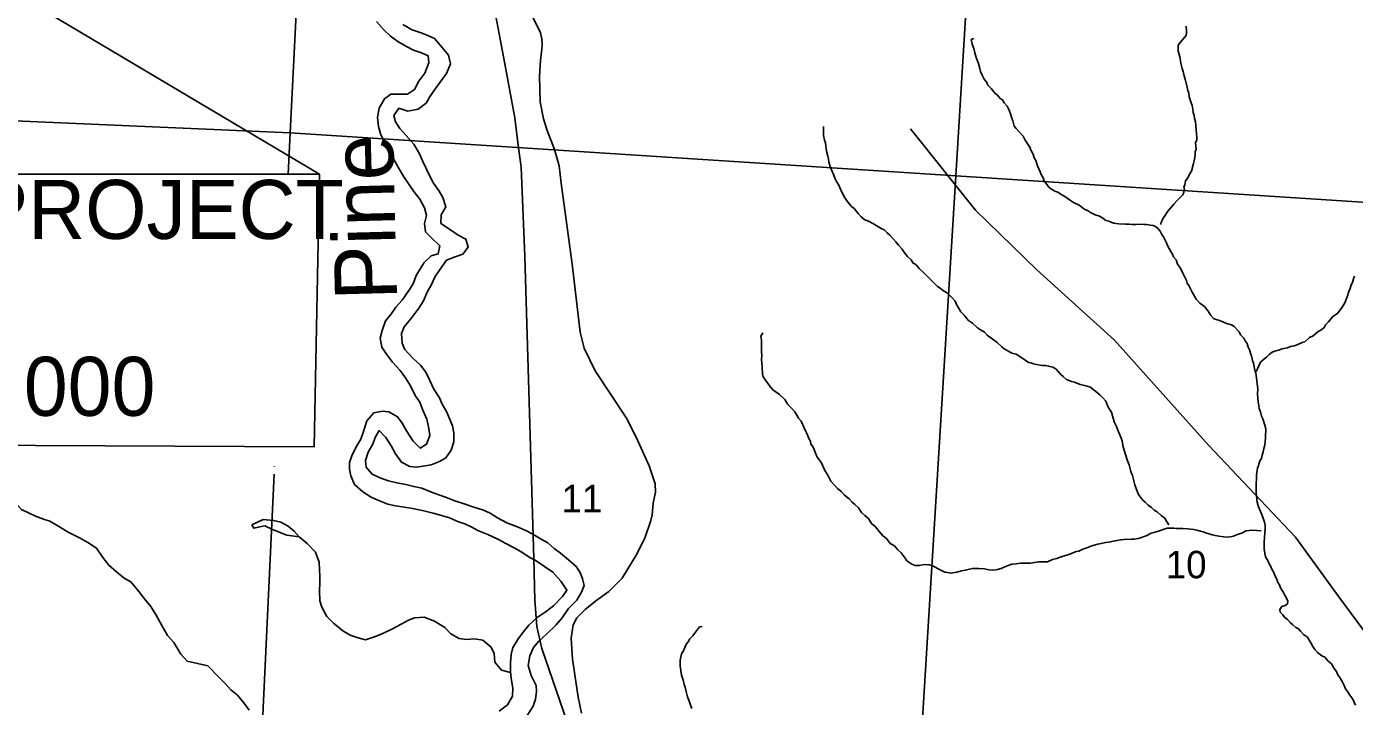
# Model space of a CAD drawing. Extents: x 0 to 82.7, y -0.2 to 22.
# Drawn here: x 3.348 to 5.374, y 17.584 to 18.621 of the extents above; entities that cross this region are included whole.
import ezdxf

# ---------------------------------------------------------------- set-up
doc = ezdxf.new("R2010")
doc.units = 0
for name, color, linetype in [('Default', 7, 'Continuous'), ('GM_X_Minor_Lake', 7, 'Continuous'), ('GM_X_Minor_River', 7, 'Continuous'), ('GM_X_Minor_River_Text', 7, 'Continuous'), ('GM_X_Rail_Line', 7, 'Continuous'), ('GM_X_Section', 7, 'Continuous'), ('GM_X_Section_Text', 7, 'Continuous'), ('GM_X_State_Route', 7, 'Continuous'), ('GM_X_Township_Road', 7, 'Continuous'), ('SH_Data', 7, 'Continuous')]:
    doc.layers.add(name, color=color, linetype=linetype)

msp = doc.modelspace()

# ---------------------------------------------------------------- linework, layer by layer
at = {"layer": 'Default'}
msp.add_lwpolyline([(3.7948, 18.3961), (3.7869, 17.9798), (2.8306, 17.9843), (2.8367, 18.3961)], dxfattribs=at)
at = {"layer": 'GM_X_Minor_Lake'}
for points in [[(3.7639, 17.8425), (3.7564, 17.8511), (3.7473, 17.8591), (3.736, 17.8649), (3.7247, 17.8676), (3.7091, 17.8689), (3.6917, 17.861)], [(3.6917, 17.861), (3.695, 17.8557), (3.7015, 17.8571), (3.7117, 17.8594), (3.7234, 17.8536), (3.7453, 17.8451), (3.7639, 17.8425)]]:
    msp.add_lwpolyline(points, dxfattribs=at)
at = {"layer": 'GM_X_Minor_River'}
for points in [[(3.8822, 18.6291), (3.8936, 18.6158), (3.9035, 18.607), (3.9145, 18.5987), (3.9278, 18.591), (3.9385, 18.5853), (3.9506, 18.5811), (3.9609, 18.5766), (3.962, 18.5663), (3.9559, 18.5504), (3.9468, 18.5382), (3.9399, 18.5253), (3.9293, 18.5181), (3.9038, 18.5181), (3.8943, 18.5113), (3.886, 18.4968), (3.8837, 18.4824), (3.8848, 18.4687), (3.8886, 18.4561), (3.8958, 18.4428), (3.9038, 18.4272), (3.9106, 18.4147), (3.9171, 18.4033), (3.9235, 18.3923), (3.9322, 18.3793), (3.9391, 18.3698), (3.9482, 18.358), (3.955, 18.3447), (3.9581, 18.3329), (3.9554, 18.3208), (3.9565, 18.3082), (3.966, 18.2987), (3.9785, 18.2865), (3.9763, 18.2744), (3.9652, 18.2717), (3.9546, 18.2611), (3.9424, 18.2413), (3.9378, 18.2288), (3.9314, 18.2185), (3.9211, 18.2037), (3.9116, 18.1931), (3.904, 18.1821), (3.8956, 18.1722), (3.8907, 18.1574), (3.8876, 18.1456), (3.8903, 18.1323), (3.8971, 18.1216), (3.9062, 18.1091), (3.918, 18.0962), (3.9263, 18.0855), (3.9339, 18.0733), (3.9411, 18.0585), (3.948, 18.0479), (3.9529, 18.0361), (3.959, 18.0224), (3.9616, 18.0079), (3.9631, 17.9973), (3.9582, 17.984), (3.9487, 17.9779), (3.9381, 17.9886), (3.9278, 18.0045), (3.921, 18.0159), (3.9141, 18.0258), (3.9008, 18.0335), (3.8913, 18.0346), (3.8777, 18.0316), (3.867, 18.0194), (3.8624, 18.0031), (3.8579, 17.9917), (3.8506, 17.9788), (3.8442, 17.9662), (3.8407, 17.956), (3.8407, 17.9457), (3.8426, 17.9358), (3.8483, 17.9225), (3.8612, 17.9115), (3.8738, 17.9031), (3.884, 17.8985)], [(3.9653, 17.9523), (3.9779, 17.9576), (3.9878, 17.9629), (3.9958, 17.9747), (4, 17.9876), (4, 18.0013), (3.9981, 18.012), (3.9893, 18.0329), (3.9821, 18.045), (3.978, 18.0546), (3.9696, 18.0682), (3.9635, 18.0812), (3.9571, 18.0937), (3.9491, 18.1048), (3.9373, 18.1154), (3.9252, 18.1287), (3.9214, 18.1382), (3.9203, 18.1531), (3.9241, 18.1629), (3.9343, 18.1751), (3.9465, 18.1914), (3.9537, 18.2028), (3.9594, 18.2161), (3.9652, 18.2268), (3.9716, 18.2397), (3.9789, 18.2511), (3.9887, 18.2647), (4.0021, 18.2697), (4.0138, 18.2738), (4.0218, 18.2849), (4.0184, 18.297), (4.0066, 18.3031), (3.9949, 18.3111), (3.98, 18.321), (3.9808, 18.3339), (3.9877, 18.3465), (3.9831, 18.3605), (3.9778, 18.37), (3.9687, 18.3826), (3.9637, 18.3921), (3.9584, 18.4039), (3.9527, 18.4153), (3.947, 18.4282), (3.9387, 18.4419), (3.9273, 18.4552), (3.9178, 18.4659), (3.911, 18.4758), (3.9083, 18.4857), (3.9163, 18.4967), (3.9296, 18.4921), (3.9456, 18.4951), (3.9577, 18.5046), (3.9638, 18.5153), (3.9718, 18.527), (3.9889, 18.5498), (3.995, 18.5643), (3.9916, 18.5776), (3.9821, 18.5894), (3.9704, 18.6031), (3.9605, 18.608), (3.9502, 18.6118), (3.9365, 18.6164), (3.9221, 18.6248)], [(5.0777, 18.3194), (5.0793, 18.3235), (5.0813, 18.3277), (5.0847, 18.3326), (5.089, 18.3397), (5.0928, 18.3435), (5.0986, 18.3506), (5.1028, 18.3555), (5.112, 18.3645), (5.1136, 18.3687), (5.1144, 18.3725), (5.1137, 18.3763), (5.1149, 18.3801), (5.1161, 18.3857), (5.1195, 18.3903), (5.1219, 18.3952), (5.1254, 18.4008), (5.1285, 18.4122), (5.1293, 18.4163), (5.1306, 18.4247), (5.131, 18.4304), (5.1322, 18.4342), (5.1315, 18.4441), (5.1331, 18.4486), (5.1332, 18.4532), (5.1328, 18.4573), (5.1325, 18.4642), (5.1318, 18.4699), (5.1312, 18.476), (5.1297, 18.4817), (5.1294, 18.4855), (5.1279, 18.4901), (5.1272, 18.4954), (5.1261, 18.5011), (5.1247, 18.5049), (5.1225, 18.511), (5.1217, 18.5148), (5.121, 18.5198), (5.1196, 18.5236), (5.1181, 18.5312), (5.1159, 18.5389), (5.1141, 18.5461), (5.1123, 18.5526), (5.1112, 18.5572), (5.1101, 18.5617), (5.109, 18.5655), (5.1083, 18.5697), (5.1073, 18.5751), (5.1062, 18.5789), (5.1051, 18.5838), (5.1047, 18.5876), (5.1048, 18.593), (5.1083, 18.5975), (5.1137, 18.6035), (5.1171, 18.6076), (5.1175, 18.6118), (5.1176, 18.6156), (5.1173, 18.6221)], [(5.104, 18.259), (5.1018, 18.2655), (5.0977, 18.2701), (5.0962, 18.2739), (5.0936, 18.2781), (5.0914, 18.2827), (5.0888, 18.2873), (5.0873, 18.2915), (5.0851, 18.2953), (5.0825, 18.3003), (5.0798, 18.3041), (5.0776, 18.3091), (5.0743, 18.3129), (5.0705, 18.316), (5.0667, 18.3176), (5.0626, 18.3184), (5.0565, 18.3192), (5.0523, 18.3193), (5.0459, 18.3198), (5.0402, 18.3191), (5.0345, 18.3195), (5.0303, 18.3196), (5.0246, 18.3196), (5.0144, 18.3205), (5.0064, 18.3214), (4.9989, 18.3242), (4.9947, 18.3253), (4.9902, 18.3288), (4.9849, 18.3319), (4.9785, 18.3343), (4.9714, 18.3374), (4.9668, 18.3405), (4.9627, 18.3421), (4.9537, 18.349), (4.945, 18.353), (4.9405, 18.3561), (4.9307, 18.363), (4.9265, 18.365), (4.9213, 18.3685), (4.9167, 18.37), (4.9118, 18.3731), (4.9081, 18.3758), (4.9028, 18.3824), (4.9006, 18.3862), (4.8991, 18.3904), (4.8961, 18.3954), (4.8943, 18.3996), (4.8921, 18.4045), (4.8902, 18.4091), (4.8877, 18.4168), (4.8854, 18.421), (4.884, 18.4248), (4.8829, 18.4286), (4.8803, 18.4328), (4.8784, 18.4374), (4.8747, 18.4435), (4.8717, 18.4481), (4.8684, 18.4542), (4.862, 18.4615), (4.8579, 18.4658), (4.8549, 18.4696), (4.8538, 18.4734), (4.8527, 18.4776), (4.8509, 18.4818), (4.849, 18.4883), (4.8476, 18.4921), (4.8461, 18.4959), (4.8439, 18.5001), (4.8397, 18.5051), (4.8371, 18.5094), (4.8334, 18.5117), (4.8293, 18.5167), (4.8255, 18.5194), (4.8195, 18.5267), (4.8146, 18.5321), (4.8128, 18.5359), (4.8087, 18.5412), (4.8057, 18.5474), (4.8035, 18.5527), (4.8024, 18.5573), (4.8002, 18.5649), (4.7973, 18.5726), (4.7958, 18.5779), (4.7944, 18.5836), (4.7933, 18.5878), (4.7907, 18.5947), (4.7893, 18.6015), (4.7931, 18.6034)], [(4.6268, 18.3266), (4.6215, 18.3309), (4.6166, 18.3362), (4.6106, 18.3435), (4.6065, 18.347), (4.6028, 18.3509), (4.599, 18.3562), (4.596, 18.3608), (4.5934, 18.3654), (4.5897, 18.3734), (4.5875, 18.3795), (4.5838, 18.3849), (4.5816, 18.3891), (4.579, 18.3956), (4.5757, 18.4036), (4.5742, 18.4078), (4.572, 18.4143), (4.5717, 18.4196), (4.5706, 18.4235), (4.5688, 18.4292), (4.5677, 18.4345), (4.5674, 18.4395), (4.5667, 18.444), (4.5656, 18.4478), (4.5641, 18.4551), (4.5638, 18.46), (4.5639, 18.4688)], [(5.0907, 17.861), (5.0869, 17.8663), (5.0843, 17.8713), (5.0791, 17.8752), (5.0727, 17.8806), (5.0682, 17.8833), (5.0644, 17.8875), (5.0591, 17.891), (5.0546, 17.8956), (5.0505, 17.8991), (5.0442, 17.9072), (5.0412, 17.9148), (5.0386, 17.922), (5.0354, 17.9361), (5.0328, 17.9423), (5.0303, 17.9525), (5.0277, 17.9587), (5.0244, 17.9682), (5.0226, 17.9747), (5.0207, 17.9819), (5.0197, 17.9892), (5.0178, 17.9934), (5.016, 17.9983), (5.0138, 18.0029), (5.0108, 18.0109), (5.0075, 18.0182), (5.0031, 18.0327), (4.9983, 18.0403), (4.9946, 18.0495), (4.9901, 18.0545), (4.986, 18.0587), (4.9792, 18.0645), (4.9751, 18.0676), (4.9709, 18.0711), (4.9641, 18.0731), (4.96, 18.0743), (4.9554, 18.0751), (4.9467, 18.0786), (4.9422, 18.0798), (4.9346, 18.0826), (4.9298, 18.0868), (4.926, 18.0903), (4.9189, 18.0987), (4.9136, 18.1015), (4.9072, 18.1031), (4.9026, 18.1039), (4.8981, 18.1043), (4.8943, 18.1047), (4.889, 18.1056), (4.8841, 18.1064), (4.8803, 18.108), (4.8765, 18.1088), (4.8716, 18.1122), (4.8634, 18.1177), (4.8577, 18.1212), (4.8513, 18.1231), (4.8452, 18.1266), (4.8396, 18.1294), (4.8358, 18.1325), (4.8287, 18.139), (4.8212, 18.1448), (4.8137, 18.1506), (4.8092, 18.1552), (4.8035, 18.1587), (4.7986, 18.1614), (4.7911, 18.1687), (4.7851, 18.173), (4.7813, 18.1768), (4.7783, 18.1811), (4.7735, 18.1861), (4.7697, 18.1922), (4.7664, 18.1983), (4.7645, 18.2021), (4.7608, 18.2067), (4.7563, 18.2114), (4.7526, 18.2148), (4.7469, 18.2179), (4.7416, 18.2222), (4.7379, 18.2245), (4.7334, 18.2295), (4.7274, 18.2349), (4.7191, 18.2434), (4.7154, 18.2468), (4.7101, 18.2515), (4.7045, 18.258), (4.7007, 18.2603), (4.6974, 18.2653), (4.6921, 18.2707), (4.6865, 18.2776), (4.6839, 18.2818), (4.6783, 18.2876), (4.6742, 18.293), (4.6693, 18.2983), (4.6652, 18.3029), (4.661, 18.3064), (4.6565, 18.3114), (4.652, 18.3134), (4.6441, 18.318), (4.6403, 18.3204), (4.6324, 18.3243), (4.6268, 18.3266)], [(5.2606, 17.7274), (5.2599, 17.7319), (5.263, 17.7361), (5.2679, 17.7379), (5.2718, 17.7405), (5.2722, 17.7443), (5.2703, 17.7489), (5.2674, 17.7535), (5.2644, 17.7592), (5.261, 17.7646), (5.2596, 17.7692), (5.257, 17.773), (5.2555, 17.7779), (5.2525, 17.7833), (5.2507, 17.7883), (5.2477, 17.7932), (5.2462, 17.7974), (5.2433, 17.8024), (5.2418, 17.8066), (5.2388, 17.8108), (5.2377, 17.8146), (5.2359, 17.8242), (5.2361, 17.8352), (5.2365, 17.8405), (5.237, 17.8496), (5.2374, 17.8542), (5.2375, 17.8606), (5.2364, 17.8648), (5.2346, 17.8713), (5.232, 17.8778), (5.2287, 17.8847), (5.2272, 17.8885), (5.2254, 17.8954), (5.225, 17.8999), (5.2243, 17.9052), (5.224, 17.9102), (5.2241, 17.9163), (5.2238, 17.9235), (5.2243, 17.9315), (5.2243, 17.936), (5.2248, 17.941), (5.226, 17.9474), (5.2272, 17.9516), (5.2295, 17.9584), (5.2318, 17.9621), (5.233, 17.9671), (5.2346, 17.9724), (5.2358, 17.9773), (5.237, 17.9826), (5.2378, 17.9879), (5.2383, 17.9936), (5.2383, 17.9993), (5.2388, 18.0035), (5.2384, 18.0073), (5.2373, 18.013), (5.234, 18.0225), (5.2322, 18.0267), (5.2304, 18.0336), (5.2285, 18.0382), (5.2278, 18.0427), (5.2268, 18.0485), (5.2264, 18.0542), (5.2261, 18.0606), (5.2262, 18.0682), (5.2259, 18.0724), (5.2256, 18.0762), (5.2245, 18.0853), (5.2231, 18.0926), (5.2216, 18.0972), (5.2198, 18.1074), (5.2184, 18.1116), (5.2173, 18.1166), (5.2158, 18.1215), (5.2136, 18.128), (5.2118, 18.1322), (5.2099, 18.1376), (5.2073, 18.1418), (5.2051, 18.146), (5.2002, 18.151), (5.198, 18.1556), (5.1901, 18.1637), (5.186, 18.166), (5.1788, 18.1684), (5.1732, 18.1707), (5.1679, 18.1727), (5.163, 18.1743), (5.1588, 18.1758), (5.1547, 18.1805), (5.1506, 18.187), (5.145, 18.1943), (5.1378, 18.1993), (5.1322, 18.2054), (5.13, 18.21), (5.1263, 18.2161), (5.1211, 18.2261), (5.1184, 18.2299), (5.1174, 18.2337), (5.1151, 18.2391), (5.1118, 18.2448), (5.1085, 18.2525), (5.104, 18.259)], [(5.2239, 18.0948), (5.2258, 18.099), (5.2281, 18.1035), (5.2305, 18.1092), (5.2343, 18.1126), (5.2401, 18.1174), (5.2439, 18.1208), (5.2485, 18.1245), (5.2523, 18.126), (5.2595, 18.1282), (5.2637, 18.1297), (5.2717, 18.1311), (5.2763, 18.1329), (5.2824, 18.134), (5.2873, 18.1362), (5.2938, 18.1392), (5.298, 18.1403), (5.3053, 18.1466), (5.311, 18.1492), (5.3183, 18.156), (5.3225, 18.1578), (5.3275, 18.1623), (5.3294, 18.1661), (5.334, 18.1706), (5.3406, 18.1788), (5.3478, 18.1837), (5.3548, 18.1931), (5.359, 18.1999), (5.3625, 18.209), (5.3653, 18.2169), (5.3672, 18.2218), (5.3688, 18.2271), (5.3707, 18.2309), (5.3723, 18.2362), (5.3739, 18.2404)], [(4.6325, 17.8706), (4.6269, 17.8752), (4.622, 17.8799), (4.6175, 17.8868), (4.6119, 17.8921), (4.6074, 17.8956), (4.6029, 17.9006), (4.5961, 17.906), (4.5909, 17.9118), (4.5852, 17.9164), (4.5811, 17.921), (4.5751, 17.9276), (4.5707, 17.9367), (4.5658, 17.944), (4.5606, 17.9555), (4.5543, 17.9643), (4.5517, 17.9704), (4.5495, 17.9761), (4.5476, 17.9803), (4.5447, 17.9842), (4.5439, 17.9884), (4.5417, 17.9926), (4.5388, 17.9991), (4.5365, 18.0044), (4.5343, 18.009), (4.5299, 18.019), (4.5258, 18.0239), (4.5232, 18.0282), (4.5202, 18.0335), (4.5149, 18.0389), (4.5097, 18.0447), (4.5048, 18.0523), (4.4966, 18.06), (4.4868, 18.067), (4.4819, 18.0724), (4.4752, 18.0816), (4.4719, 18.0866), (4.4708, 18.0915), (4.4701, 18.1014), (4.4698, 18.1079), (4.4695, 18.1132), (4.4696, 18.1193), (4.4693, 18.125), (4.4695, 18.1428), (4.4684, 18.1489), (4.4711, 18.1542)], [(4.1118, 17.5698), (4.1209, 17.5842), (4.1247, 17.5949), (4.1263, 17.6063), (4.1255, 17.6158), (4.1179, 17.631), (4.1134, 17.6462), (4.1157, 17.661), (4.1214, 17.6736), (4.1294, 17.6831), (4.1411, 17.6941), (4.156, 17.7081), (4.1651, 17.7191), (4.175, 17.7332), (4.1875, 17.7457), (4.1948, 17.7579), (4.1986, 17.7685), (4.1963, 17.7784), (4.1925, 17.7879), (4.1868, 17.7974), (4.175, 17.8077), (4.1629, 17.8176), (4.153, 17.8248), (4.1431, 17.8336), (4.1333, 17.8389), (4.123, 17.845), (4.1116, 17.8511), (4.0979, 17.8572), (4.0808, 17.8637), (4.0664, 17.8716), (4.0554, 17.8789), (4.0451, 17.8835), (4.0303, 17.888), (4.0155, 17.893), (4.0014, 17.8976), (3.9874, 17.9029), (3.9771, 17.9067), (3.9661, 17.9109), (3.9513, 17.9166), (3.9387, 17.9193), (3.9269, 17.9223), (3.9129, 17.925), (3.9003, 17.928), (3.8886, 17.9322), (3.8753, 17.9383), (3.8661, 17.949), (3.865, 17.9589), (3.8692, 17.9718), (3.8764, 17.9839), (3.8799, 17.9942), (3.8859, 18.0048), (3.8962, 17.9942), (3.9042, 17.9813), (3.911, 17.9691), (3.9201, 17.9565), (3.933, 17.9501), (3.9429, 17.9489), (3.9532, 17.9504), (3.9653, 17.9523)], [(3.3287, 17.8968), (3.3406, 17.8844), (3.362, 17.874), (3.3742, 17.8696), (3.3837, 17.8666), (3.3982, 17.858), (3.4116, 17.8498), (3.4287, 17.8412), (3.4417, 17.8341), (3.4547, 17.8255), (3.4643, 17.8108), (3.4735, 17.7991), (3.4854, 17.789), (3.4969, 17.7796), (3.5072, 17.7737), (3.5195, 17.7593), (3.5279, 17.748), (3.5379, 17.736), (3.5457, 17.7232), (3.5541, 17.7084), (3.5634, 17.6918), (3.5726, 17.6813), (3.5834, 17.6635), (3.5934, 17.653)], [(3.884, 17.8985), (3.8992, 17.8924), (3.911, 17.8898), (3.9209, 17.8886), (3.9342, 17.8863), (3.9444, 17.8844), (3.9543, 17.8821), (3.9684, 17.8787), (3.9813, 17.8749), (3.9931, 17.8718), (4.0071, 17.8654), (4.0166, 17.8623), (4.0273, 17.8574), (4.0368, 17.8524), (4.052, 17.8459), (4.0679, 17.8383), (4.0793, 17.8326), (4.0919, 17.8257), (4.1037, 17.8193), (4.1147, 17.8113), (4.1242, 17.8067), (4.1382, 17.7972), (4.1511, 17.7884), (4.1633, 17.7748), (4.1724, 17.7614), (4.1656, 17.7516), (4.1522, 17.7371), (4.1393, 17.7276), (4.1271, 17.7193), (4.1142, 17.7075), (4.1055, 17.6969), (4.0986, 17.6874), (4.0899, 17.6737), (4.0876, 17.6631), (4.0864, 17.6501), (4.0864, 17.6372), (4.0876, 17.6262), (4.0898, 17.6114), (4.0894, 17.5996), (4.0818, 17.5863), (4.0689, 17.5764)], [(5.2317, 17.8516), (5.2249, 17.8524), (5.2169, 17.8525), (5.2131, 17.8522), (5.2082, 17.8515), (5.2032, 17.8489), (5.1986, 17.8471), (5.1941, 17.8456), (5.1891, 17.8434), (5.1815, 17.8423), (5.1747, 17.8428), (5.1671, 17.8437), (5.1618, 17.8445), (5.1569, 17.8457), (5.152, 17.8469), (5.1467, 17.8489), (5.1429, 17.8501), (5.1387, 17.8512), (5.1334, 17.8528), (5.1289, 17.8536), (5.1194, 17.8549), (5.1119, 17.8554), (5.102, 17.8555), (5.0982, 17.8559), (5.0929, 17.856), (5.0883, 17.8557), (5.0834, 17.8542), (5.0765, 17.8517), (5.0697, 17.8498), (5.0636, 17.848), (5.0563, 17.8439), (5.0476, 17.841), (5.0438, 17.8399), (5.0377, 17.8392), (5.0339, 17.8389), (5.0221, 17.8383), (5.0168, 17.838), (5.0115, 17.8369), (5.0062, 17.8362), (4.9989, 17.8344), (4.9944, 17.8341), (4.9822, 17.8312), (4.9769, 17.8297), (4.9731, 17.8287), (4.9654, 17.8257), (4.9594, 17.8239), (4.9533, 17.8209), (4.9495, 17.8202), (4.9395, 17.8162), (4.935, 17.8147), (4.9296, 17.8133), (4.9235, 17.811), (4.9197, 17.8096), (4.9133, 17.8081), (4.9053, 17.8044), (4.9007, 17.8045), (4.892, 17.8042), (4.8855, 17.8032), (4.8798, 17.8025), (4.8741, 17.8022), (4.8646, 17.8023), (4.8578, 17.8012), (4.851, 17.8006), (4.8453, 17.7987), (4.8403, 17.7969), (4.835, 17.7943), (4.8293, 17.7929), (4.8236, 17.7918), (4.8163, 17.7923), (4.8092, 17.7935), (4.8008, 17.7944), (4.7955, 17.7944), (4.791, 17.7941), (4.7868, 17.793), (4.7807, 17.7916), (4.7742, 17.7909), (4.767, 17.7887), (4.7575, 17.7869), (4.7529, 17.7881), (4.7488, 17.7886), (4.745, 17.7905), (4.7378, 17.7944), (4.7318, 17.7979), (4.725, 17.7999), (4.7201, 17.8003), (4.7148, 17.7996), (4.7102, 17.7989), (4.7038, 17.799), (4.6985, 17.801), (4.6909, 17.806), (4.6883, 17.8099), (4.6824, 17.8183), (4.6771, 17.8225), (4.6722, 17.8287), (4.6658, 17.8326), (4.6602, 17.8399), (4.6542, 17.8441), (4.6475, 17.8529), (4.6426, 17.8583), (4.6373, 17.8629), (4.6325, 17.8706)], [(3.7639, 17.8425), (3.7763, 17.8322), (3.7888, 17.8192), (3.7944, 17.8039), (3.7951, 17.7925), (3.7958, 17.7826), (3.7957, 17.7712), (3.7952, 17.7606), (3.7955, 17.745), (3.7985, 17.7351), (3.8064, 17.721), (3.8162, 17.711), (3.8306, 17.6991), (3.8419, 17.6926), (3.8541, 17.6883), (3.8651, 17.6852), (3.8807, 17.6904), (3.8925, 17.6957), (3.9066, 17.702), (3.9196, 17.7091), (3.9307, 17.7155), (3.9402, 17.7189), (3.9547, 17.7199), (3.9706, 17.7137), (3.9861, 17.7041), (3.9952, 17.6945), (4.008, 17.6872), (4.0191, 17.686), (4.0316, 17.6867), (4.0441, 17.6847), (4.057, 17.674), (4.0615, 17.6644), (4.0626, 17.6515), (4.0727, 17.6393), (4.0864, 17.6354)], [(5.3754, 17.5857), (5.3736, 17.5903), (5.3714, 17.5949), (5.3669, 17.601), (5.3632, 17.6064), (5.3602, 17.6106), (5.358, 17.6159), (5.3554, 17.6205), (5.3513, 17.6278), (5.3483, 17.632), (5.3464, 17.637), (5.3427, 17.6416), (5.3386, 17.6488), (5.3337, 17.6527), (5.3285, 17.6589), (5.324, 17.6608), (5.3176, 17.6662), (5.3134, 17.6704), (5.3101, 17.6754), (5.3075, 17.6808), (5.3045, 17.685), (5.3023, 17.6896), (5.2963, 17.6935), (5.2914, 17.6985), (5.2884, 17.7023), (5.2842, 17.7043), (5.2797, 17.7081), (5.2756, 17.7116), (5.2719, 17.7166), (5.2673, 17.7197), (5.2647, 17.7235), (5.2606, 17.7274)], [(4.3628, 17.5807), (4.3606, 17.5872), (4.3584, 17.5933), (4.3562, 17.5983), (4.3544, 17.6063), (4.3526, 17.6131), (4.3511, 17.617), (4.3497, 17.6238), (4.3475, 17.6315), (4.346, 17.6387), (4.345, 17.6452), (4.3451, 17.6543), (4.3475, 17.6641), (4.3502, 17.6686), (4.3525, 17.6736), (4.3545, 17.6789), (4.3579, 17.6826), (4.3595, 17.6864), (4.3645, 17.6913), (4.3672, 17.695), (4.3749, 17.7052), (4.3787, 17.7055)], [(3.5934, 17.653), (3.6245, 17.6459), (3.6411, 17.6287), (3.651, 17.6187), (3.6596, 17.6092), (3.6698, 17.6011), (3.6796, 17.5893), (3.6879, 17.5782)]]:
    msp.add_lwpolyline(points, dxfattribs=at)
at = {"layer": 'GM_X_Rail_Line'}
msp.add_lwpolyline([(4.2049, 17.4668), (4.1341, 17.672), (4.1268, 17.7058), (4.1236, 17.746), (4.122, 17.8096), (4.1083, 18.2707), (4.1027, 18.4067), (4.0987, 18.4365), (4.0931, 18.4823), (4.0778, 18.5644), (4.0464, 18.7318)], dxfattribs=at)
at = {"layer": 'GM_X_Section'}
msp.add_line((3.7263, 17.9497), (3.7263, 17.9503), dxfattribs=at)
for points in [[(2.8166, 19.5355), (3.8012, 19.4723), (3.7502, 18.459), (2.7471, 18.503)], [(3.8012, 19.4723), (4.8277, 19.4092), (4.7658, 18.3936), (3.7502, 18.459)], [(4.8277, 19.4092), (5.8471, 19.3468), (5.7783, 18.3279), (4.7658, 18.3936)], [(4.7658, 18.3936), (5.7783, 18.3279), (5.7068, 17.3032), (4.7026, 17.3656)]]:
    msp.add_lwpolyline(points, close=True, dxfattribs=at)
msp.add_lwpolyline([(3.7473, 18.3959), (3.7502, 18.459), (4.7658, 18.3936), (4.7026, 17.3656), (3.7019, 17.4301), (3.7258, 17.938)], dxfattribs=at)
at = {"layer": 'GM_X_State_Route'}
msp.add_lwpolyline([(4.1946, 17.5735), (4.1895, 17.598), (4.1809, 17.6556), (4.1791, 17.6879), (4.1821, 17.7081), (4.1878, 17.719), (4.2002, 17.7314), (4.2167, 17.7447), (4.2364, 17.7589), (4.2565, 17.7795), (4.278, 17.8147), (4.2913, 17.8404), (4.3004, 17.8674), (4.3023, 17.8761), (4.3041, 17.894), (4.3078, 17.9105), (4.3069, 17.9233), (4.2977, 17.9508), (4.2783, 17.9948), (4.2634, 18.0236), (4.2154, 18.0959), (4.1989, 18.1306), (4.1928, 18.1548), (4.1804, 18.2587), (4.1739, 18.3075), (4.1635, 18.3825), (4.1606, 18.4086), (4.1535, 18.4338), (4.1421, 18.4627), (4.1369, 18.4807), (4.1317, 18.5064), (4.1305, 18.5456), (4.1322, 18.5696), (4.1341, 18.5871), (4.1346, 18.5938), (4.1341, 18.6022), (4.132, 18.6118), (4.1201, 18.6369)], dxfattribs=at)
at = {"layer": 'GM_X_Township_Road'}
msp.add_lwpolyline([(5.4722, 17.5578), (5.4644, 17.583), (5.451, 17.6143), (5.3499, 17.7511), (5.2837, 17.842), (5.1514, 17.9826), (5.008, 18.1425), (4.8895, 18.2501), (4.7957, 18.341), (4.6965, 18.4651)], dxfattribs=at)
at = {"layer": 'SH_Data'}
msp.add_lwpolyline([(3.7948, 18.3961), (2.779, 19.0002), (2.8367, 18.3961)], close=True, dxfattribs=at)

# ---------------------------------------------------------------- texts
at = {"layer": 'Default'}
for s, p in [('BEGIN PROJECT', (2.8624, 18.2973)), ('S.L.M. 0.000', (2.8624, 18.0273))]:
    msp.add_text(s, height=0.09, dxfattribs=at).set_placement(p)
at = {"layer": 'GM_X_Minor_River_Text'}
msp.add_text('Pine', height=0.09469, rotation=91.493, dxfattribs=at).set_placement((3.9135, 18.2046))
at = {"layer": 'GM_X_Section_Text'}
for s, p in [('11', (4.1642, 17.8801)), ('10', (5.0859, 17.7793))]:
    msp.add_text(s, height=0.04186, rotation=0, dxfattribs=at).set_placement(p)

doc.saveas('drawing.dxf')
